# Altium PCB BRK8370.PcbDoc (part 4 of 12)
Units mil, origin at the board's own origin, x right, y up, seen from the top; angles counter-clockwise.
Board outline 8267.72 x 5708.66 mil, 6 copper layers (L1-TOP, L2-GND, L3-PWR, L4-PWR, L5-GND, L6-BOT), stack 68.606 mil thick; 319 components, 516 nets, 2008 pads, 1743 vias.
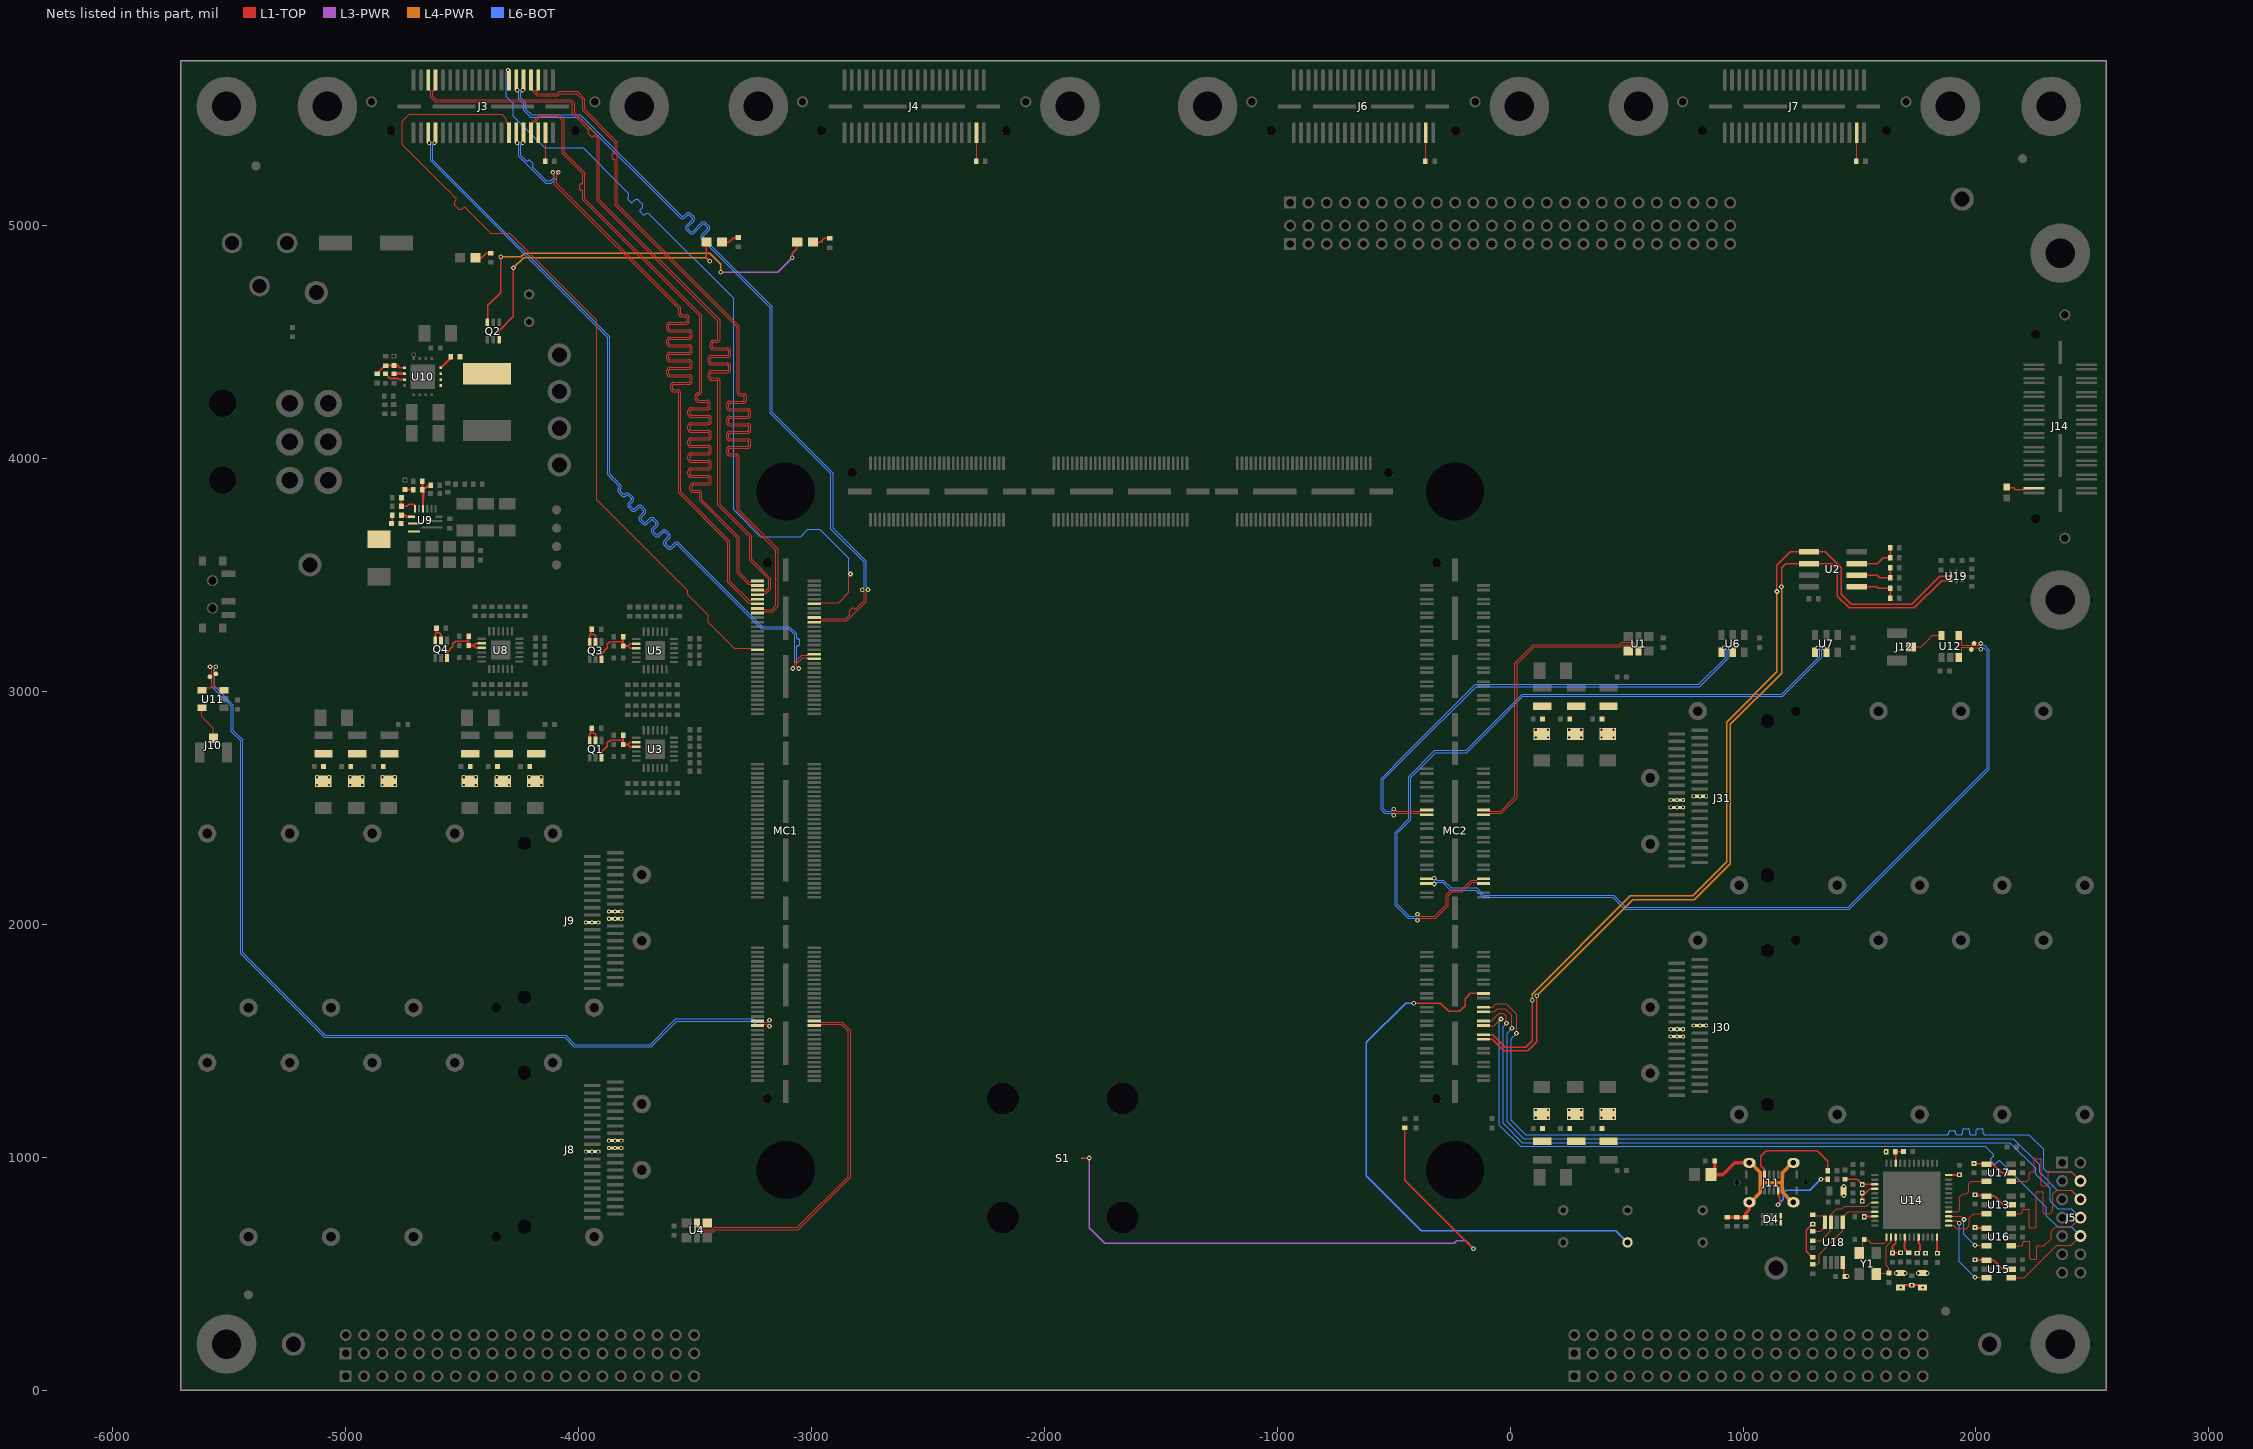
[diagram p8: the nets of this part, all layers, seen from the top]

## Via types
v1: diameter 20, hole 10, L1-TOP to L6-BOT, tented both sides, 957 vias
v2: diameter 18, hole 10, L1-TOP to L6-BOT, tented both sides, 786 vias

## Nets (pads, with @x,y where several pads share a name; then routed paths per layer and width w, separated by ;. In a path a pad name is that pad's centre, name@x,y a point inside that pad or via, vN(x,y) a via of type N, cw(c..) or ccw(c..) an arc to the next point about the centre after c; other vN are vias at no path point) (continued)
EECS: R101.2 U14.45 U18.1 | length 415.2
  L1-TOP w4.96: R101.2@1299.21,539.37 1318.9,539.37 1326.77,547.24 1326.77,582.68 1428.15,684.06 U18.1@1428.15,720.47 1434.53,726.85 1434.53,748.31 1451.97,765.75 U14.45@1565.94,765.75
EEDATA: R102.1 U14.43 U18.3 | length 374.8
  L1-TOP w4.96: R102.1@1299.21,641.73 1334.54,641.73 1376.97,684.17 U18.3@1376.97,720.47 1376.97,753.18 1402.63,778.84 1425.88,778.84 1436.62,789.58 1529.74,789.58 1545.28,805.12 U14.43@1565.94,805.12
EEPROM_A0: R6.1 R9.2 U2.1 | length 189
  L1-TOP w6: U2.1@1488.19,3448.62 1575,3448.62 1579.95,3443.67 R6.1@1631.86,3443.67 R9.2@1631.86,3400.36
EEPROM_A1: R5.1 R8.2 U2.2 | length 191.8
  L1-TOP w6: U2.2@1488.19,3498.62 1576.18,3498.62 1587.83,3486.98 R8.2@1631.86,3486.98 R5.1@1631.86,3530.28
EEPROM_A2: R3.1 R7.2 U2.3 | length 197.3
  L1-TOP w6: U2.3@1488.19,3548.62 1576.18,3548.62 1601.15,3573.59 R7.2@1631.86,3573.59 R3.1@1631.86,3616.9
EEPROM_DO: R102.2 R103.1 U18.4 | length 158.5
  L1-TOP w4.96: R102.2@1299.21,681.1 1334.65,681.1 1345.52,691.98 1345.52,714.61 U18.4@1351.38,720.47 1351.38,740.16 1342.52,749.02 1302.17,749.02 R103.1@1299.21,751.97
FPGA_JTAG_TCK: J5.6 MC2.22 U13.4 | length 3951.4
  L1-TOP w4.96: MC2.22@-114.57,1624.02 -68.47,1624.02 -54.69,1637.8 -21.27,1637.8 7.9,1608.62 v1(7.9,1552.81) ; U13.4@2151.57,757.87 2190.14,757.87 2192.62,757.87 ccw(c2192.62,763.87) 2198.62,763.87 2198.62,771.17 cw(c2204.61,771.17) 2204.61,777.16 2222.59,777.16 cw(c2222.59,771.17) 2228.58,771.17 2228.58,701.84 ccw(c2234.57,701.84) 2234.57,695.85 2252.55,695.85 ccw(c2252.55,701.84) 2258.54,701.84 2258.54,846.15 cw(c2264.53,846.15) 2264.53,852.14 2282.51,852.14 cw(c2282.51,846.15) 2288.5,846.15 2288.5,763.87 ccw(c2294.5,763.87) 2294.5,757.87 2312.43,757.87 2316.81,757.87 2330.4,771.46 2330.4,842.03 2346.64,858.27 2409.45,858.27 J5.6@2448.82,818.9
  L6-BOT w4.96: v1(7.9,1552.81) -13.03,1531.88 -13.03,1151.82 59.02,1079.78 2161,1079.78 2274.08,966.69 2274.08,934.52 2350.33,858.27 2409.45,858.27 J5.6@2448.82,818.9
FPGA_JTAG_TDI: J5.10 MC2.18 U15.4 | length 3673.1
  L1-TOP w4.96: MC2.18@-114.57,1564.96 -67.81,1564.96 v1(-39.44,1593.33) ; U15.4@2151.57,482.28 2207.3,482.28 2347.07,622.05 2409.45,622.05 J5.10@2448.82,661.42
  L6-BOT w4.96: v1(-39.44,1593.33) -39.44,1590.7 -46.95,1583.19 -46.95,1137.77 44.97,1045.85 2040.33,1045.85 2054.56,1031.62 2056.31,1029.87 2074.53,1011.65 cw(c2070.29,1007.41) 2074.53,1003.17 2064.31,992.96 ccw(c2068.55,988.72) 2064.31,984.48 2077.03,971.77 ccw(c2081.26,976.01) 2085.5,971.77 2095.72,981.99 cw(c2099.96,977.75) 2104.19,981.99 2105.95,980.23 2301.93,784.25 2301.93,749.37 2350.52,700.79 2409.45,700.79 J5.10@2448.82,661.42
FPGA_JTAG_TDO: J5.8 MC2.20 U16.4 | length 3781.9
  L1-TOP w4.96: MC2.20@-114.57,1584.65 -79.8,1584.65 -47.27,1617.18 -28.88,1617.18 -15.75,1604.05 v1(-15.75,1574.8) ; U16.4@2151.57,620.08 2193.59,620.08 2196.07,620.08 ccw(c2196.07,626.07) 2202.07,626.07 2202.07,633.38 cw(c2208.06,633.38) 2208.06,639.37 2226.04,639.37 cw(c2226.04,633.38) 2232.03,633.38 2232.03,567 ccw(c2238.02,567) 2238.02,561 2256,561 ccw(c2256,567) 2261.99,567 2261.99,614.09 cw(c2267.99,614.09) 2267.99,620.08 2293.31,620.08 2294.17,620.94 2322.83,649.61 2322.83,681.1 2342.52,700.79 2409.45,700.79 J5.8@2448.82,740.16
  L6-BOT w4.96: v1(-15.75,1574.8) -29.99,1560.56 -29.99,1144.8 51.99,1062.82 2145.85,1062.82 2257.12,951.54 2257.12,927.49 2318.9,865.72 2318.9,811.52 2351.29,779.12 2409.85,779.12 J5.8@2448.82,740.16
FPGA_JTAG_TMS: J5.4 MC2.24 U17.4 | length 3897.9
  L1-TOP w4.96: MC2.24@-114.57,1643.7 -75.32,1643.7 -61.42,1657.6 -16.32,1657.6 27.56,1613.72 v1(27.56,1531.5) ; U17.4@2151.57,895.67 2218.5,895.67 2228.35,905.51 2228.35,929.13 2236.22,937.01 2242.51,937.01 2244.99,937.01 ccw(c2244.99,943) 2250.98,943 2250.98,987.75 cw(c2256.97,987.75) 2256.97,993.75 2274.95,993.75 cw(c2274.95,987.75) 2280.94,987.75 2280.94,882.31 ccw(c2286.94,882.31) 2286.94,876.31 2304.91,876.31 ccw(c2304.91,882.31) 2310.91,882.31 2310.91,931.02 cw(c2316.9,931.02) 2316.9,937.01 2341.6,937.01 2409.45,937.01 J5.4@2448.82,897.64
  L6-BOT w4.96: v1(27.56,1531.5) 3.94,1507.87 3.94,1158.85 66.05,1096.74 1842.52,1096.74 1876.62,1096.74 ccw(c1876.62,1102.73) 1882.61,1102.73 1882.61,1107.25 cw(c1888.61,1107.25) 1888.61,1113.25 1906.58,1113.25 cw(c1906.58,1107.25) 1912.58,1107.25 1912.58,1102.73 ccw(c1918.57,1102.73) 1918.57,1096.74 1936.55,1096.74 ccw(c1936.55,1102.73) 1942.54,1102.73 1942.54,1115.75 cw(c1948.53,1115.75) 1948.53,1121.74 1966.51,1121.74 cw(c1966.51,1115.75) 1972.5,1115.75 1972.5,1102.73 ccw(c1978.5,1102.73) 1978.5,1096.74 1996.47,1096.74 ccw(c1996.47,1102.73) 2002.47,1102.73 2002.47,1115.75 cw(c2008.46,1115.75) 2008.46,1121.74 2026.44,1121.74 cw(c2026.44,1115.75) 2032.43,1115.75 2032.43,1102.73 ccw(c2038.42,1102.73) 2038.42,1096.74 2070.87,1096.74 2227.19,1096.74 2291.05,1032.89 2291.05,950.93 2304.97,937.01 2409.45,937.01 J5.4@2448.82,897.64
FT232_RESET: C76.2 R96.1 U14.34 | length 86.1
  L1-TOP w6: U14.34@1655.51,973.43 1655.51,1021.65 R96.1@1653.54,1023.62 C76.2@1688.58,1023.62
FT232_VCCD: C7.2 C58.2 C62.2 C63.2 C64.2 C68.2 C69.2 C70.2 C74.2 C80.2 C82.2 FB1.1 FB2.1 R96.2 R100.2 R103.2 U13.1 U13.5 U14.12 U14.24 U14.39 U14.46 U15.1 U15.5 U16.1 U17.1 U17.5 U18.8 | length 1226.5
  L1-TOP w6: R100.2@1299.21,570.87 1297.24,570.87 1271.65,596.46 1271.65,687.01 1297.24,712.6 v1(1299.21,712.6)
  L1-TOP w8: U18.8@1428.15,547.24 1432.78,542.62 1432.78,495.02 1434.48,493.31 1442.52,493.31 C82.2@1437.4,488.19 v1(1447.64,488.19) ; C68.2@1437.01,905.12 1489.57,905.12 1512.2,882.48 v1(1512.2,881.89) 1513.82,883.51 1565.59,883.51 U14.39@1565.94,883.86 ; v1(1520.08,744.09) 1521.69,745.71 1565.59,745.71 U14.46@1565.94,746.06 ; U14.12@1832.68,656.5 1832.76,656.42 1832.76,589.29 v1(1834.65,587.4) ; U14.24@1882.87,923.23 1883.23,923.58 1927.91,923.58 v1(1929.13,924.8) ; v1(1992.13,972.83) 1993.31,971.65 2044.09,971.65 U17.1@2045.28,970.47 2072.83,970.47 2110.24,933.07 U17.5@2151.57,933.07 ; v1(1996.06,559.84) 1997.44,558.46 2043.9,558.46 U15.1@2045.28,557.09 2076.77,557.09 2114.17,519.69 U15.5@2151.57,519.69 ; v1(1996.06,697.64) 1997.44,696.26 2043.9,696.26 U16.1@2045.28,694.88 ; v1(1996.06,838.98) 1999.21,835.83 2042.13,835.83 U13.1@2045.28,832.68 2080.71,832.68 2118.11,795.28 U13.5@2151.57,795.28
  L1-TOP w10: v1(1677.17,440.16) 1683.66,440.16 1694.43,450.92 C7.2@1723.88,450.92 ; C7.2@1724.94,450.92 1754.39,450.92 1765.16,440.16 v1(1771.65,440.16)
  other v1: 1724.41,450.39 1614.17,1023.62
FT232_VREGIN: C66.2 C67.2 FB3.1 U14.40 | length 97.1
  L1-TOP w8: v1(1512.2,811.02) v1(1512.2,846.46) ; C67.2@1512.2,847.05 v1(1512.2,846.46) ; U14.40@1565.94,864.17 1545.22,864.17 1527.5,846.46 v1(1512.2,846.46)
  other v1: 1432.28,835.04 1432.28,873.62
FTDI_TCK: U13.3 U14.13 | length 215.8
  L1-TOP w4.96: U14.13@1882.87,706.69 1903.54,706.69 1917.32,692.91 1960.63,692.91 1972.44,704.72 1972.44,740.16 1990.16,757.87 U13.3@2045.28,757.87
FTDI_TDI: U14.14 U15.3 | length 360.4
  L1-TOP w4.96: U14.14@1882.87,726.38 1919.29,726.38 v1(1929.13,716.54) ; v1(1996.06,484.25) 2043.31,484.25 U15.3@2045.28,482.28
  L6-BOT w4.96: v1(1929.13,716.54) 1929.13,551.18 v1(1996.06,484.25)
FTDI_TDO: U14.15 U16.3 | length 251.5
  L1-TOP w4.96: U14.15@1882.87,746.06 1935.04,746.06 v1(1948.82,732.28) ; v1(1996.06,622.05) 2043.31,622.05 U16.3@2045.28,620.08
  L6-BOT w4.96: v1(1948.82,732.28) 1948.82,669.29 v1(1996.06,622.05)
FTDI_TMS: U14.16 U17.3 | length 269.3
  L1-TOP w4.96: U14.16@1882.87,765.75 1923.23,765.75 1931.55,774.07 1931.55,829.19 1944.88,842.52 1960.63,842.52 1968.5,850.39 1968.5,885.83 1978.35,895.67 U17.3@2045.28,895.67
FX3_SCL_1V8: MC2.14 U2.6 U19.3 | length 3818.6
  L1-TOP w6: MC2.14@-114.57,1505.91 -76.77,1505.91 -27.56,1456.69 74.8,1456.69 114.17,1496.06 v1(114.17,1692.91) ; v1(1165.35,3448.82) 1165.35,3530.95 1183.03,3548.62 U2.6@1283.46,3548.62 1380.51,3548.62 1405.51,3523.62 1405.51,3409.45 1456.69,3358.27 1736.22,3358.27 1852.36,3474.41 U19.3@1892.52,3474.41
  L4-PWR w6: v1(114.17,1692.91) 527.56,2106.3 791.34,2106.3 944.88,2259.84 944.88,2858.27 1165.35,3078.74 v1(1165.35,3448.82)
FX3_SDA_1V8: MC2.16 U2.5 U19.2 | length 3856.2
  L1-TOP w6: MC2.16@-114.57,1525.59 -74.67,1525.59 -21.52,1472.44 66.93,1472.44 94.49,1500 v1(94.49,1673.23) ; v1(1145.67,3429.13) 1145.67,3542.22 1202.07,3598.62 U2.5@1283.46,3598.62 1354.13,3598.62 1421.26,3531.5 1421.26,3417.32 1464.57,3374.02 1724.41,3374.02 1844.49,3494.09 U19.2@1892.52,3494.09
  L4-PWR w6: v1(94.49,1673.23) 94.49,1699.78 516.76,2122.05 783.46,2122.05 929.13,2267.72 929.13,2867.69 1145.67,3084.22 v1(1145.67,3429.13)
GNDADC: MC2.28 TP4.1 | length 2450.2
  L1-TOP w6: v1(-413.39,1661.42) -299.21,1661.42 -263.78,1625.98 -216.54,1625.98 -192.91,1649.61 -192.91,1681.1 -171.26,1702.76 MC2.28@-114.57,1702.76
  L6-BOT w6: v1(-413.39,1661.42) -448.82,1661.42 -617.31,1492.93 -617.31,919.89 -381.91,684.49 453.3,684.49 TP4.1@503.94,633.86
MGTREFCLK0_130: J10.1 U11.5 | length 151.4
  L1-TOP w4.96: U11.5@-5617.26,2929.17 -5617.26,2891.76 -5567.91,2842.42 J10.1@-5567.91,2798.23
MGTREFCLK0_227: J12.1 U12.5 | length 151.4
  L1-TOP w4.96: J12.1@1721.43,3190.81 1765.61,3190.81 1814.96,3240.16 U12.5@1852.36,3240.16
MGTREFCLK0N_129: MC1.28 U4.5 | length 1584.8
  L1-TOP w3.3: U4.5@-3492.13,716.54 -3492.13,709.65 -3480.98,698.5 -3478.43,698.5 -3476.5,696.57 -3476.5,687.08 -3469.29,679.88 -3419.74,679.88 -3410.57,689.05 -3056.47,689.05 -2832.39,913.13 -2832.39,1543.56 -2868.13,1579.3 -2935.44,1579.3 -2944.58,1579.3 -2960.6,1579.3 -2965.94,1584.65 MC1.28@-2988.58,1584.65
MGTREFCLK0N_130: MC1.27 TP24.1 U11.3 | length 3959.2
  L1-TOP w3.3: v1(-5557.51,3105.69) -5557.51,3103.41 -5565.51,3095.41 -5565.51,3060.24 -5565.52,3018.03 -5563.58,3016.1 -5534.9,3016.1 U11.3@-5522.77,3003.97 ; MC1.27@-3231.89,1584.65 -3209.25,1584.65 -3203.91,1579.3 -3199.59,1579.3 -3190.6,1579.3 -3182.6,1587.3 v1(-3180.32,1587.3)
  L6-BOT w3.3: v1(-5557.51,3105.69) -5557.51,3103.41 -5565.51,3095.41 -5565.51,3073.68 -5565.52,3024.55 -5482,2941.04 -5482,2830.8 -5442.71,2791.51 -5442.71,1878.13 -5087.41,1522.83 -4055.82,1522.83 -4016.12,1483.13 -3692.61,1483.13 -3582.37,1593.36 -3250.19,1593.36 -3236.13,1579.3 -3190.6,1579.3 -3182.6,1587.3 v1(-3180.32,1587.3)
MGTREFCLK0N_225: MC2.67 U6.5 | length 2097.8
  L1-TOP w3.3: v1(-500,2493.5) -497.72,2493.5 -489.72,2485.5 -471.51,2485.5 -470.82,2484.82 -433.07,2484.82 -385.85,2484.82 -380.51,2490.16 MC2.67@-357.87,2490.16 ; v1(944.59,3187.99) 956.69,3175.89 U6.5@956.69,3167.32
  L6-BOT w3.3: v1(-500,2493.5) -502.28,2493.5 -510.28,2485.5 -534.34,2485.5 -544.99,2496.16 -544.99,2621.79 -433.07,2733.71 -145.97,3020.81 -61.42,3020.81 814.49,3020.81 936.59,3142.9 936.59,3177.71 944.59,3185.71 v1(944.59,3187.99)
MGTREFCLK0N_226: MC2.68 U1.5 | length 1329.9
  L1-TOP w3.3: MC2.68@-114.57,2490.16 -91.93,2490.16 -86.59,2484.82 -70.57,2484.82 -61.42,2484.82 -41.15,2484.82 20.81,2546.78 20.81,3121.74 99.74,3200.67 469.58,3200.67 478.8,3209.89 528.35,3209.89 535.55,3202.68 535.55,3193.2 537.49,3191.26 540.04,3191.26 551.18,3180.12 U1.5@551.18,3173.23
MGTREFCLK0N_227: MC2.47 TP26.1 U12.3 | length 3346
  L1-TOP w3.3: U12.3@1927.17,3145.67 1939.29,3157.8 1939.29,3186.48 1941.23,3188.41 1975.42,3188.41 1975.52,3188.31 2010.36,3188.31 2018.36,3180.31 v1(2020.64,3180.31)
  L6-BOT w3.3: v1(-325.98,2197.54) -323.7,2197.54 -315.7,2189.54 -286.18,2189.54 -252.35,2155.71 -143.93,2155.71 -112.51,2124.3 -61.42,2124.3 445.14,2124.3 496.32,2073.12 1452.66,2073.12 2048.37,2668.83 2048.37,3173.72 2033.78,3188.31 2030.92,3188.31 2022.92,3180.31 v1(2020.64,3180.31)
MGTREFCLK0N_228: MC2.48 U7.5 | length 3108.7
  L1-TOP w3.3: v1(-397.64,2042.31) -395.35,2042.31 -387.35,2034.31 -322.94,2034.31 -274.49,2082.75 -274.49,2127.06 -253.07,2148.48 -208.36,2148.48 -167.3,2189.54 -142.55,2189.54 -137.2,2194.88 MC2.48@-114.57,2194.88 ; v1(1346.16,3187.99) 1358.27,3175.89 U7.5@1358.27,3167.32
  L6-BOT w3.3: v1(-397.64,2042.31) -399.92,2042.31 -407.92,2034.31 -433.07,2034.31 -433.54,2034.31 -485.38,2086.15 -485.38,2390.23 -433.07,2442.54 -426.88,2448.72 -426.88,2629.83 -319.36,2737.35 -185.51,2737.35 -61.42,2861.43 55.21,2978.06 1169.55,2978.06 1338.16,3146.68 1338.16,3177.71 1346.16,3185.71 v1(1346.16,3187.99)
MGTREFCLK0P_129: MC1.26 U4.4 | length 1540.8
  L1-TOP w3.3: U4.4@-3447.83,716.54 -3448.82,716.54 -3466.85,698.5 -3466.85,697.21 -3467.5,696.57 -3467.5,690.81 -3465.57,688.88 -3423.47,688.88 -3414.3,698.05 -3060.2,698.05 -2841.39,916.86 -2841.39,1539.84 -2871.86,1570.3 -2935.44,1570.3 -2940.86,1570.3 -2960.6,1570.3 -2965.94,1564.96 MC1.26@-2988.58,1564.96
MGTREFCLK0P_130: MC1.25 TP23.1 U11.4 | length 3974.1
  L1-TOP w3.3: U11.4@-5617.26,3003.97 -5605.13,3016.1 -5576.45,3016.1 -5574.52,3018.03 -5574.52,3059.06 -5574.52,3064.73 -5574.51,3095.41 -5582.51,3103.41 v1(-5582.51,3105.69) ; MC1.25@-3231.89,1564.96 -3209.25,1564.96 -3203.91,1570.3 -3195.86,1570.3 -3190.6,1570.3 -3182.6,1562.3 v1(-3180.32,1562.3)
  L6-BOT w3.3: v1(-5582.51,3105.69) -5582.51,3103.41 -5574.51,3095.41 -5574.51,3078.18 -5574.52,3020.83 -5491,2937.31 -5491,2827.08 -5451.71,2787.79 -5451.71,1874.4 -5091.14,1513.83 -4059.55,1513.83 -4019.85,1474.13 -3688.88,1474.13 -3578.65,1584.36 -3253.92,1584.36 -3239.86,1570.3 -3190.6,1570.3 -3182.6,1562.3 v1(-3180.32,1562.3)
MGTREFCLK0P_225: MC2.65 U6.4 | length 2112.7
  L1-TOP w3.3: v1(-500,2468.5) -497.72,2468.5 -489.72,2476.5 -475.23,2476.5 -474.54,2475.82 -433.07,2475.82 -385.85,2475.82 -380.51,2470.47 MC2.65@-357.87,2470.47 ; U6.4@907.48,3167.32 919.59,3179.43 v1(919.59,3187.99)
  L6-BOT w3.3: v1(-500,2468.5) -502.28,2468.5 -510.28,2476.5 -538.07,2476.5 -553.99,2492.43 -553.99,2625.52 -433.07,2746.44 -149.7,3029.81 -61.42,3029.81 810.77,3029.81 927.59,3146.63 927.59,3177.71 919.59,3185.71 v1(919.59,3187.99)
MGTREFCLK0P_226: MC2.66 U1.4 | length 1315.7
  L1-TOP w3.3: MC2.66@-114.57,2470.47 -91.93,2470.47 -86.59,2475.82 -66.84,2475.82 -61.42,2475.82 -37.42,2475.82 29.81,2543.05 29.81,3118.02 103.47,3191.67 473.31,3191.67 482.53,3200.89 524.62,3200.89 526.55,3198.95 526.55,3193.2 525.91,3192.55 525.91,3191.26 507.87,3173.23 U1.4@506.89,3173.23
MGTREFCLK0P_227: MC2.45 TP25.1 U12.4 | length 3375.8
  L1-TOP w3.3: U12.4@1927.17,3240.16 1939.29,3228.03 1939.29,3199.35 1941.23,3197.41 1979.14,3197.41 1979.25,3197.31 2010.36,3197.31 2018.36,3205.31 v1(2020.64,3205.31)
  L6-BOT w3.3: v1(-325.98,2172.54) -323.7,2172.54 -315.7,2180.54 -289.91,2180.54 -256.08,2146.71 -147.65,2146.71 -116.24,2115.3 -61.42,2115.3 441.41,2115.3 492.59,2064.12 1456.39,2064.12 2057.37,2665.1 2057.37,3177.45 2037.51,3197.31 2030.92,3197.31 2022.92,3205.31 v1(2020.64,3205.31)
MGTREFCLK0P_228: MC2.46 U7.4 | length 3123.6
  L1-TOP w3.3: v1(-397.64,2017.31) -395.35,2017.31 -387.35,2025.31 -319.21,2025.31 -265.49,2079.03 -265.49,2123.33 -249.34,2139.48 -204.63,2139.48 -163.57,2180.54 -142.55,2180.54 -137.2,2175.2 MC2.46@-114.57,2175.2 ; U7.4@1309.06,3167.32 1321.16,3179.43 v1(1321.16,3187.99)
  L6-BOT w3.3: v1(-397.64,2017.31) -399.92,2017.31 -407.92,2025.31 -433.07,2025.31 -437.26,2025.31 -494.38,2082.42 -494.38,2393.96 -435.88,2452.45 -435.88,2633.55 -433.07,2636.37 -323.09,2746.35 -189.23,2746.35 -61.42,2874.15 51.49,2987.06 1165.82,2987.06 1329.16,3150.41 1329.16,3177.71 1321.16,3185.71 v1(1321.16,3187.99)
NetC9_2: C9.2 C57.2 FB1.2 U14.8 | length 76.8
  L1-TOP w8: v1(1748.03,587.4) 1748.62,587.4 1754.86,593.64 1754.86,594.23 1759.84,599.21 1759.84,625.98 1753.94,631.89 U14.8@1753.94,656.5
  other v1: 1752.36,501.57 1790.94,501.57 1783.46,587.4
NetC10_2: C10.2 Q1.6 R2.1 U3.20 U3.21 | length 288
  L1-TOP w6: Q1.6@-3901.57,2714.57 -3901.57,2739.69 -3875.98,2765.28 -3875.98,2779.53 -3865.03,2790.48 -3835.27,2790.48 -3835.19,2790.4 -3808.86,2790.4
  L1-TOP w8: R2.1@-3809.06,2811.02 -3808.86,2810.83 -3808.86,2790.4 -3808.86,2771.85 C10.2@-3808.66,2771.65 -3788.33,2771.65 ; U3.21@-3751.97,2761.81 -3778.49,2761.81 -3788.33,2771.65 ; U3.20@-3751.97,2781.5 -3778.49,2781.5 -3788.33,2771.65
NetC13_2: C13.2 C14.2 J8.30 L1.2
  other v2: -3869.77,1070.87 -3843.31,1070.87 -3816.84,1070.87 -4841.95,2598.09 -4789.95,2598.09 -4841.95,2631.01 -4789.95,2631.01
NetC15_2: C15.2 C16.2 J8.29 L2.2
  other v2: -3869.77,1039.37 -3843.31,1039.37 -3816.84,1039.37 -5123.44,2598.09 -5071.44,2598.09 -5123.44,2631.01 -5071.44,2631.01
NetC17_2: C17.2 C18.2 J8.10 L3.2
  other v2: -3968.59,1023.62 -3942.13,1023.62 -3915.66,1023.62 -4980.72,2598.09 -4928.72,2598.09 -4980.72,2631.01 -4928.72,2631.01
NetC21_2: C21.2 C22.2 J9.30 L4.2
  other v2: -3869.77,2055.12 -3843.31,2055.12 -3816.84,2055.12 -4212.02,2598.09 -4160.02,2598.09 -4212.02,2631.01 -4160.02,2631.01
NetC23_2: C23.2 C24.2 J9.29 L11.2
  other v2: -3869.77,2023.62 -3843.31,2023.62 -3816.84,2023.62 -4493.52,2598.09 -4441.52,2598.09 -4493.52,2631.01 -4441.52,2631.01
NetC25_2: C25.2 C26.2 J9.10 L12.2
  other v2: -3968.59,2007.87 -3942.13,2007.87 -3915.66,2007.87 -4350.8,2598.09 -4298.8,2598.09 -4350.8,2631.01 -4298.8,2631.01
NetC31_2: C31.2 Q3.6 R35.1 U5.20 U5.21 | length 288
  L1-TOP w6: Q3.6@-3901.57,3137.8 -3901.57,3161.12 -3875.98,3186.71 -3875.98,3202.76 -3865.03,3213.71 -3835.27,3213.71 -3835.19,3213.63 -3808.86,3213.63
  L1-TOP w8: R35.1@-3809.06,3234.25 -3808.86,3234.06 -3808.86,3213.63 -3808.86,3195.08 C31.2@-3808.66,3194.88 -3788.33,3194.88 ; U5.21@-3751.97,3185.04 -3778.49,3185.04 -3788.33,3194.88 ; U5.20@-3751.97,3204.72 -3778.49,3204.72 -3788.33,3194.88
NetC33_2: C33.2 Q4.6 R55.1 U8.20 U8.21 | length 284.1
  L1-TOP w6: Q4.6@-4564.96,3143.7 -4564.96,3167.32 -4539.37,3192.91 -4539.37,3204.72 -4528.42,3215.68 -4498.65,3215.68 -4498.58,3215.6 -4472.24,3215.6
  L1-TOP w8: R55.1@-4472.44,3236.22 -4472.24,3236.02 -4472.24,3215.6 -4472.24,3197.05 C33.2@-4472.05,3196.85 -4451.72,3196.85 ; U8.21@-4415.35,3187.01 -4441.88,3187.01 -4451.72,3196.85 ; U8.20@-4415.35,3206.69 -4441.88,3206.69 -4451.72,3196.85
NetC39_1: C39.1 R64.2 | length 37.8
  L1-TOP w6: C39.1@-4803.11,3720.59 -4799.92,3723.78 R64.2@-4799.92,3757.1
NetC39_2: C39.2 L13.1 U9.2 U9.3
NetC40_1: C40.1 R68.2 | length 34.7
  L1-TOP w9: C40.1@-4744.76,3867.03 -4711.36,3867.03 R68.2@-4710.44,3866.11
NetC53_1: C53.1 U10.12 | length 67.2
  L1-TOP w10: U10.12@-4593.71,4390.37 -4589.73,4390.37 -4549.41,4430.69 C53.1@-4549.41,4436.87
NetC53_2: C53.2 L14.1 U10.9 U10.10 U10.11
NetC54_1: C54.1 R77.1 R78.2 U10.1 | length 138.8
  L1-TOP w8: R78.2@-4865.25,4363.55 -4865.25,4366.87 -4832.94,4399.18 -4829.25,4399.18 R77.1@-4828.86,4398.79 -4793.25,4398.79 -4776.17,4398.79 -4767.15,4389.76 U10.1@-4747.05,4389.76
NetC55_2: C55.2 U10.3 | length 92.7
  L1-TOP w8: C55.2@-4829.25,4363.94 -4808.11,4342.81 -4774.19,4342.81 -4769.97,4338.58 U10.3@-4747.05,4338.58
NetC56_2: C56.2 U10.2 | length 46.3
  L1-TOP w13: C56.2@-4793.25,4363.94 -4793.02,4364.17 U10.2@-4747.05,4364.17
NetC60_2: C60.2 C61.2 FB2.2 U14.3 | length 108.8
  L1-TOP w7: v1(1641.73,588.98) 1641.93,589.17 v1(1676.97,589.17) C61.2@1677.17,589.37
  L1-TOP w8: v1(1641.73,588.98) 1641.73,617.28 1655.51,631.06 U14.3@1655.51,656.5
  other v1: 1657.87,501.57 1696.46,501.57
NetC77_2: C77.2 FB4.1 J11.M1 J11.M2 J11.M3 J11.M4 R97.1 R98.1 R99.1 | length 924.3
  L1-TOP w15: C77.2@878.35,984.25 878.35,965.93 878.33,941.32 FB4.1@862.2,925.2 913.39,925.2 963.78,975.59 J11.M3@1027.56,975.59 ; R97.1@933.07,742.13 R98.1@972.44,742.13 R99.1@1011.81,742.13 1011.81,759.84 1027.56,775.59 J11.M2@1027.56,806.3
  L4-PWR w15: J11.M2@1027.56,806.3 1032.48,806.3 1074.8,848.62 1074.8,890.94 ; J11.M3@1027.56,975.59 1032.48,975.59 1074.8,933.27 1074.8,890.94 ; J11.M1@1216.54,806.3 1211.61,806.3 1169.29,848.62 1169.29,890.94 ; J11.M4@1216.54,975.59 1211.61,975.59 1169.29,933.27 1169.29,890.94 ; 1074.8,890.94 1169.29,890.94
NetC78_2: C78.2 U14.1 Y1.1 | length 189.8
  L1-TOP w4.96: Y1.1@1499.02,588.58 1514.75,604.32 1514.75,640.34 C78.2@1520.08,645.67 1535.43,645.67 1551.18,629.92 1607.39,629.92 1616.14,638.68 U14.1@1616.14,656.5
NetC79_2: C79.2 U14.2 Y1.3 | length 223.9
  L1-TOP w4.96: Y1.3@1571.85,498.03 1576.18,502.36 C79.2@1625.98,502.36 1625.98,523.62 1614.17,535.43 1614.17,618.11 1635.83,639.76 U14.2@1635.83,656.5
NetC90_2: C90.2 C91.2 J30.29 L6.2
  other v2: 253.31,1169.29 305.31,1169.29 253.31,1202.21 305.31,1202.21 689.68,1549.21 716.14,1549.21 742.61,1549.21
NetC92_2: C92.2 C93.2 J30.10 L7.2
  other v2: 110.6,1169.29 162.6,1169.29 110.6,1202.21 162.6,1202.21 788.5,1564.96 814.96,1564.96 841.43,1564.96
NetC94_2: C94.2 C95.2 J30.30 L5.2
  other v2: 392.09,1169.29 444.09,1169.29 392.09,1202.21 444.09,1202.21 689.68,1517.72 716.14,1517.72 742.61,1517.72
NetC102_2: C102.2 C103.2 J31.29 L9.2
  other v2: 689.68,2533.46 716.14,2533.46 742.61,2533.46 392.09,2801.72 444.09,2801.72 392.09,2834.65 444.09,2834.65
NetC104_2: C104.2 C105.2 J31.10 L10.2
  other v2: 788.5,2549.21 814.96,2549.21 841.43,2549.21 110.6,2801.72 162.6,2801.72 110.6,2834.65 162.6,2834.65
NetC106_2: C106.2 C107.2 J31.30 L8.2
  other v2: 689.68,2501.97 716.14,2501.97 742.61,2501.97 253.31,2801.72 305.31,2801.72 253.31,2834.65 305.31,2834.65
NetD1_2: D1.2 R4.1 | length 73.1
  L1-TOP w6: D1.2@-4442.91,4862.2 -4415.63,4862.2 -4395.95,4881.89 R4.1@-4377.95,4881.89
NetD2_1: D2.1 Q2.6 | length 1289.8
  L1-TOP w6: Q2.6@-4340.55,4509.84 -4340.55,4548.73 -4279.53,4609.75 v1(-4279.53,4818.9) ; D2.1@-3450.79,4929.13 -3450.79,4860.24 v1(-3437.01,4846.46)
  L4-PWR w6: v1(-4279.53,4818.9) -4236.15,4862.27 -3452.82,4862.27 v1(-3437.01,4846.46)
NetD2_2: D2.2 R12.1 | length 77.1
  L1-TOP w6: D2.2@-3383.86,4929.13 -3354.33,4929.13 -3334.65,4948.82 R12.1@-3314.96,4948.82
NetD3_1: D3.1 Q2.3 | length 1720.6
  L1-TOP w6: Q2.3@-4391.73,4584.65 -4389.76,4586.61 -4389.76,4657.48 -4334.65,4712.6 v1(-4334.65,4866.14) ; v1(-3082.68,4862.2) -3082.68,4881.89 -3062.99,4901.57 -3062.99,4927.17 D3.1@-3061.02,4929.13
  L3-PWR w6: v1(-3389.76,4799.21) -3145.67,4799.21 v1(-3082.68,4862.2)
  L4-PWR w6: v1(-4334.65,4866.14) -4247.84,4866.14 -4232.09,4881.89 -3437.01,4881.89 -3389.76,4834.65 v1(-3389.76,4799.21)
NetD3_2: D3.2 R92.1 | length 79.4
  L1-TOP w6: D3.2@-2994.09,4929.13 -2960.63,4929.13 -2944.88,4944.88 R92.1@-2921.26,4944.88
NetD4_1,10: D4.1 D4.10 | length 30.5
  L1-TOP w5: D4.10@1161.42,718.21 D4.1@1161.42,748.72
NetJ3_4: J3.4 R66.2 | length 122
  L1-TOP w5: J3.4@-4141.65,5399.01 -4141.6,5277.41 R66.2@-4141.34,5277.15
NetJ4_4: J4.4 R67.2 | length 122
  L1-TOP w5: J4.4@-2291.26,5399.01 -2291.21,5277.41 R67.2@-2290.94,5277.15
NetJ6_4: J6.4 R10.2 | length 122
  L1-TOP w5: J6.4@-362.07,5399.01 -362.07,5277.41 R10.2@-361.81,5277.15
NetJ7_4: J7.4 R11.2 | length 122
  L1-TOP w5: J7.4@1488.27,5399.01 1488.32,5277.41 R11.2@1488.58,5277.15
NetJ11_A5: J11.A5 R93.2 | length 342
  L1-TOP w6: v1(1150.25,795.84) 1150.25,799.17 1157.44,806.35 1157.44,828.18 1151.57,834.05 J11.A5@1151.57,856.89 ; v1(1334.65,905.51) R93.2@1364.17,905.51
  L6-BOT w6: v1(1150.25,795.84) 1173.23,818.82 1173.23,846.46 1185.04,858.27 1287.4,858.27 v1(1334.65,905.51)
NetJ11_B5: J11.B5 R94.1 | length 442.7
  L1-TOP w6: J11.B5@1092.52,925 1092.52,946.85 1076.53,962.84 1076.53,1003.32 1100.77,1027.56 1318.9,1027.56 1364.17,982.28 R94.1@1364.17,940.94
NetJ14_4: J14.4 R27.2 | length 122.7
  L1-TOP w6: R27.2@2132.05,3873.97 2161.46,3873.97 2169.29,3866.14 2202.62,3866.14 2205.57,3869.09 2246.7,3869.09 J14.4@2249.21,3871.6
NetQ1_2: Q1.2 Q1.3 R1.1 | length 104.1
  L1-TOP w6: Q1.3@-3952.76,2789.37 -3952.76,2816.93 -3946.85,2822.83 ; R1.1@-3946.85,2842.52 -3946.85,2822.83 ; Q1.2@-3927.17,2789.37 -3927.17,2814.96 -3935.04,2822.83 -3946.85,2822.83
NetQ3_2: Q3.2 Q3.3 R34.1 | length 104.1
  L1-TOP w6: Q3.3@-3952.76,3212.6 -3952.76,3240.16 -3946.85,3246.06 ; R34.1@-3946.85,3265.75 -3946.85,3246.06 ; Q3.2@-3927.17,3212.6 -3927.17,3238.19 -3935.04,3246.06 -3946.85,3246.06
NetQ4_2: Q4.2 Q4.3 R54.1 | length 104.1
  L1-TOP w6: Q4.3@-4616.14,3218.5 -4616.14,3246.06 -4610.24,3251.97 ; R54.1@-4610.24,3271.65 -4610.24,3251.97 ; Q4.2@-4590.55,3218.5 -4590.55,3244.09 -4598.43,3251.97 -4610.24,3251.97
NetR64_1: R64.1 U9.1 | length 45.8
  L1-TOP w9: R64.1@-4760.55,3757.1 -4745.86,3757.1 -4738.73,3749.98 U9.1@-4717.67,3749.98
NetR65_1: R65.1 R68.1 R70.2 U9.10 | length 161.8
  L1-TOP w9: R68.1@-4671.15,3866.19 -4671.15,3882.42 -4671.07,3882.5 R65.1@-4671.07,3902.11 ; U9.10@-4667.47,3784.66 -4667.14,3866.09 -4667.14,3872.01 -4665.73,3873.42 -4657.59,3873.42 -4652.53,3878.48 -4640.85,3878.48 -4635.51,3883.83 R70.2@-4635.51,3885.8
NetR71_1: R71.1 R73.2 U9.12 | length 114.2
  L1-TOP w6: R71.1@-4760.51,3830.94 R73.2@-4760.51,3793.94 -4738.2,3793.94 -4727.99,3804.15 -4709.99,3804.15 -4702.91,3797.06 U9.12@-4702.91,3784.66
NetR95_2: R95.2 U14.5 | length 77.7
  L1-TOP w8: U14.5@1694.88,656.5 1694.88,631.8 1692.82,629.74 1692.82,607.51 1696.99,603.33 1696.99,602.61 1710.63,588.98 R95.2@1712.6,588.98
NetR104_1: R104.1 S1.2 | length 2668.2
  L1-TOP w6: S1.2@-1838.56,996.06 v1(-1807.09,996.06) ; R104.1@-452.76,1125.98 -452.76,901.57 v1(-157.48,606.3)
  L3-PWR w6: v1(-1807.09,996.06) -1807.09,696.85 -1740.16,629.92 -240.29,629.92 -230.18,640.03 -191.21,640.03 v1(-157.48,606.3)
PORTA_C2P_CLK_N: J3.36 MC1.148 | length 3383
  L1-TOP w3.3: v1(-3080.12,3098.43) -3080.12,3100.71 -3072.12,3108.71 -3072.12,3123.3 -3041.32,3154.11 -3016.56,3154.11 -3011.22,3159.45 MC1.148@-2988.58,3159.45
  L6-BOT w3.3: v2(-4641.53,5355.65) -4641.53,5353.41 -4634.5,5346.37 -4634.5,5277.66 -3875.55,4518.71 -3875.55,3929.75 -3854.79,3908.99 -3851.76,3905.96 -3827.42,3881.62 cw(c-3831.42,3877.62) -3827.42,3873.61 ccw(c-3817.05,3863.25) -3827.39,3852.86 -3815.44,3840.9 ccw(c-3805.04,3851.24) -3794.68,3840.87 -3794.44,3841.11 cw(c-3790.42,3837.13) -3786.42,3841.13 -3774.41,3829.12 cw(c-3778.41,3825.12) -3774.41,3821.12 -3785.01,3810.52 ccw(c-3774.65,3800.15) -3784.99,3789.76 -3773.04,3777.81 ccw(c-3762.64,3788.14) -3752.28,3777.78 -3741.69,3788.36 cw(c-3737.67,3784.38) -3733.67,3788.38 -3721.66,3776.37 cw(c-3725.66,3772.37) -3721.66,3768.37 -3738.44,3751.59 -3738.44,3751.39 ccw(c-3726.76,3742.54) -3737.1,3732.15 ; -3737.1,3732.14 -3725.15,3720.19 ; -3725.14,3720.19 ccw(c-3714.75,3730.53) -3704.39,3720.17 -3688.94,3735.61 cw(c-3684.92,3731.63) -3680.92,3735.63 -3668.91,3723.62 cw(c-3672.91,3719.62) -3668.91,3715.62 -3685.69,3698.84 -3685.69,3698.64 ccw(c-3674.01,3689.79) -3684.35,3679.4 ; -3684.35,3679.39 -3672.4,3667.44 ; -3672.39,3667.44 ccw(c-3662,3677.78) -3651.64,3667.42 -3636.19,3682.86 cw(c-3632.17,3678.88) -3628.17,3682.88 -3616.16,3670.87 cw(c-3620.16,3666.87) -3616.16,3662.87 -3632.94,3646.09 -3632.94,3645.89 ccw(c-3621.26,3637.04) -3631.6,3626.65 ; -3631.6,3626.64 -3619.65,3614.69 ; -3619.64,3614.69 ccw(c-3609.25,3625.03) -3598.89,3614.67 -3583.68,3629.87 cw(c-3579.68,3625.87) -3575.66,3629.86 ; -3575.64,3629.85 -3574.36,3628.56 -3571.32,3625.53 -3215.2,3269.4 -3098.52,3269.4 -3072.12,3243 -3072.12,3108.71 -3080.12,3100.71 v1(-3080.12,3098.43)
PORTA_C2P_CLK_P: J3.34 MC1.146 | length 3383.1
  L1-TOP w3.3: v1(-3055.12,3098.43) -3055.12,3100.71 -3063.12,3108.71 -3063.12,3119.58 -3037.59,3145.11 -3016.56,3145.11 -3011.22,3139.76 MC1.146@-2988.58,3139.76
  L6-BOT w3.3: v2(-4618.46,5355.65) -4618.46,5353.41 -4625.5,5346.37 -4625.5,5281.39 -3866.55,4522.44 -3866.55,3933.48 -3848.43,3915.35 -3845.39,3912.32 -3821.05,3887.98 cw(c-3831.42,3877.62) -3821.05,3867.25 ccw(c-3817.05,3863.25) -3821.06,3859.25 -3809.04,3847.23 ccw(c-3805.04,3851.24) -3801.04,3847.24 -3799.47,3848.81 -3799.27,3848.81 cw(c-3790.42,3837.13) -3780.05,3847.5 -3768.05,3835.49 cw(c-3778.41,3825.12) -3768.02,3814.78 -3778.65,3804.15 ccw(c-3774.65,3800.15) -3778.66,3796.15 -3766.64,3784.14 ccw(c-3762.64,3788.14) -3758.64,3784.14 -3746.72,3796.06 -3746.52,3796.06 cw(c-3737.67,3784.38) -3727.3,3794.75 -3715.3,3782.74 cw(c-3725.66,3772.37) -3715.26,3762.04 -3730.74,3746.56 ; -3730.76,3746.54 ccw(c-3726.76,3742.54) -3730.77,3738.54 -3718.75,3726.52 ccw(c-3714.75,3730.53) -3710.75,3726.53 -3693.97,3743.31 -3693.77,3743.31 cw(c-3684.92,3731.63) -3674.55,3742 -3662.55,3729.99 cw(c-3672.91,3719.62) -3662.51,3709.29 -3677.99,3693.81 ; -3678.01,3693.79 ccw(c-3674.01,3689.79) -3678.02,3685.79 -3666,3673.77 ccw(c-3662,3677.78) -3658,3673.78 -3641.22,3690.56 -3641.02,3690.56 cw(c-3632.17,3678.88) -3621.8,3689.25 -3609.8,3677.24 cw(c-3620.16,3666.87) -3609.76,3656.54 -3625.24,3641.06 ; -3625.26,3641.04 ccw(c-3621.26,3637.04) -3625.27,3633.04 -3613.25,3621.02 ccw(c-3609.25,3625.03) -3605.25,3621.03 -3590.04,3636.24 cw(c-3579.68,3625.87) -3570.82,3637.56 -3570.63,3637.56 -3569.33,3636.26 ; -3569.31,3636.24 -3567.99,3634.92 -3564.96,3631.89 -3211.47,3278.4 -3094.79,3278.4 -3063.12,3246.73 -3063.12,3232.28 -3063.12,3230.63 ccw(c-3057.46,3230.63) -3057.46,3224.97 -3056.47,3224.97 cw(c-3056.47,3219.31) -3050.81,3219.31 -3050.81,3202.33 cw(c-3056.47,3202.33) -3056.47,3196.67 -3057.46,3196.67 ccw(c-3057.46,3191.01) -3063.12,3191.01 -3063.12,3173.23 -3063.12,3108.71 -3055.12,3100.71 v1(-3055.12,3098.43)
PORTA_P2C_CLK_N: J3.35 MC1.175 | length 3563.5
  L1-TOP w3.3: J3.35@-4645.65,5624.61 -4645.65,5587.86 -4639.3,5581.51 -4636.33,5581.51 -4634.4,5579.58 -4634.4,5550.92 -4614.66,5531.19 -4038.29,5531.19 -4026.23,5519.13 -4026.23,5480.42 -4012.8,5466.98 -3966.47,5420.65 -3957.69,5411.88 cw(c-3961.69,5407.87) -3957.69,5403.87 -3958.4,5403.17 ccw(c-3954.39,5399.17) -3958.4,5395.17 -3946.39,5383.16 ccw(c-3942.39,5387.16) -3938.38,5383.16 -3937.68,5383.86 cw(c-3933.68,5379.86) -3929.68,5383.86 -3928.51,5382.69 -3920.13,5374.32 -3920.13,5107.57 -3401.57,4589.01 -3401.57,4578.74 -3401.57,4512 cw(c-3406.23,4512) -3406.23,4507.34 -3421.42,4507.34 ccw(c-3421.42,4493.68) -3435.08,4493.68 -3435.08,4479.7 ccw(c-3421.42,4479.7) -3421.42,4466.04 -3360.86,4466.04 cw(c-3360.86,4461.38) -3356.2,4461.38 -3356.2,4447.4 cw(c-3360.86,4447.4) -3360.86,4442.74 -3429.35,4442.74 ccw(c-3429.35,4429.08) -3443.01,4429.08 -3443.01,4415.1 ccw(c-3429.35,4415.1) -3429.35,4401.44 -3360.86,4401.44 cw(c-3360.86,4396.78) -3356.2,4396.78 -3356.2,4382.8 cw(c-3360.86,4382.8) -3360.86,4378.14 -3429.35,4378.14 ccw(c-3429.35,4364.48) -3443.01,4364.48 -3443.01,4350.5 ccw(c-3429.35,4350.5) -3429.35,4336.84 -3406.23,4336.84 cw(c-3406.23,4332.18) -3401.57,4332.18 -3401.57,4326.03 -3401.57,3798.43 -3265.95,3662.81 -3265.95,3571.46 -3265.95,3562.82 -3183.91,3480.78 -3183.91,3444.18 -3198.4,3429.7 -3203.91,3429.7 -3209.25,3435.04 MC1.175@-3231.89,3435.04
PORTA_P2C_CLK_P: J3.33 MC1.173 | length 3563.5
  L1-TOP w3.3: J3.33@-4614.15,5624.61 -4614.15,5587.86 -4620.5,5581.51 -4623.47,5581.51 -4625.4,5579.58 -4625.4,5554.65 -4610.94,5540.19 -4034.56,5540.19 -4017.23,5522.86 -4017.23,5484.14 -4012.8,5479.71 -3911.13,5378.05 -3911.13,5111.3 -3392.57,4592.74 -3392.57,4578.74 -3392.57,4512 cw(c-3406.23,4512) -3406.23,4498.34 -3421.42,4498.34 ccw(c-3421.42,4493.68) -3426.08,4493.68 -3426.08,4479.7 ccw(c-3421.42,4479.7) -3421.42,4475.04 -3360.86,4475.04 cw(c-3360.86,4461.38) -3347.2,4461.38 -3347.2,4447.4 cw(c-3360.86,4447.4) -3360.86,4433.74 -3429.35,4433.74 ccw(c-3429.35,4429.08) -3434.01,4429.08 -3434.01,4415.1 ccw(c-3429.35,4415.1) -3429.35,4410.44 -3360.86,4410.44 cw(c-3360.86,4396.78) -3347.2,4396.78 -3347.2,4382.8 cw(c-3360.86,4382.8) -3360.86,4369.14 -3429.35,4369.14 ccw(c-3429.35,4364.48) -3434.01,4364.48 -3434.01,4350.5 ccw(c-3429.35,4350.5) -3429.35,4345.84 -3406.23,4345.84 cw(c-3406.23,4332.18) -3392.57,4332.18 -3392.57,4326.03 -3392.57,3802.16 -3256.95,3666.54 -3256.95,3571.46 -3256.95,3566.54 -3174.91,3484.51 -3174.91,3440.45 -3194.67,3420.7 -3203.91,3420.7 -3209.25,3415.35 MC1.173@-3231.89,3415.35
PORTA_S0_D0_P: J3.5 MC1.165 | length 3563.5
  L1-TOP w3.3: J3.5@-4173.15,5624.61 -4173.15,5587.86 -4179.5,5581.51 -4182.47,5581.51 -4184.4,5579.58 -4184.4,5576.11 -4174.78,5566.49 -4092.68,5566.49 -4083.19,5575.98 -4012.8,5575.98 -4006.54,5575.98 -3974.13,5543.56 -3974.13,5498.53 -3833.52,5357.92 -3833.52,5091.17 -3309.9,4567.55 -3309.9,4346.46 -3309.9,4283.55 ccw(c-3305.24,4283.55) -3305.24,4278.89 -3292.39,4278.89 cw(c-3292.39,4265.23) -3278.73,4265.23 -3278.73,4251.25 cw(c-3292.39,4251.25) -3292.39,4237.59 -3350.61,4237.59 ccw(c-3350.61,4232.93) -3355.27,4232.93 -3355.27,4218.95 ccw(c-3350.61,4218.95) -3350.61,4214.29 -3273.56,4214.29 cw(c-3273.56,4200.63) -3259.9,4200.63 -3259.9,4186.65 cw(c-3273.56,4186.65) -3273.56,4172.99 -3350.61,4172.99 ccw(c-3350.61,4168.33) -3355.27,4168.33 -3355.27,4154.35 ccw(c-3350.61,4154.35) -3350.61,4149.69 -3273.56,4149.69 cw(c-3273.56,4136.03) -3259.9,4136.03 -3259.9,4122.05 cw(c-3273.56,4122.05) -3273.56,4108.39 -3350.61,4108.39 ccw(c-3350.61,4103.73) -3355.27,4103.73 -3355.27,4089.75 ccw(c-3350.61,4089.75) -3350.61,4085.09 -3273.56,4085.09 cw(c-3273.56,4071.43) -3259.9,4071.43 -3259.9,4057.45 cw(c-3273.56,4057.45) -3273.56,4043.79 -3350.61,4043.79 ccw(c-3350.61,4039.13) -3355.27,4039.13 -3355.27,4025.15 ccw(c-3350.61,4025.15) -3350.61,4020.49 -3323.56,4020.49 cw(c-3323.56,4006.83) -3309.9,4006.83 -3309.9,4000.68 -3309.9,3776.97 -3143.42,3610.49 -3143.42,3571.46 -3143.42,3365.88 -3167.35,3341.96 -3203.91,3341.96 -3209.25,3336.61 MC1.165@-3231.89,3336.61
PORTA_S1_D1_P: J3.6 MC1.177 | length 3564.4
  L1-TOP w3.3: J3.6@-4173.15,5399.01 -4173.15,5435.76 -4179.5,5442.11 -4182.47,5442.11 -4184.4,5444.04 -4184.4,5447.51 -4161.74,5470.17 -4089.56,5470.17 -4069.79,5450.4 -4069.79,5311.37 -3981.73,5223.31 -3981.73,5215.05 -3981.73,5185.1 cw(c-3987.39,5185.1) -3987.39,5179.44 -3988.38,5179.44 ccw(c-3988.38,5173.78) -3994.04,5173.78 -3994.04,5156.8 ccw(c-3988.38,5156.8) -3988.38,5151.14 -3987.39,5151.14 cw(c-3987.39,5145.48) -3981.73,5145.48 -3981.73,5124.73 -3981.73,5111.67 -3480.32,4610.26 -3480.32,4322.83 -3480.32,4287.57 cw(c-3484.98,4287.57) -3484.98,4282.91 ccw(c-3484.98,4269.25) -3498.64,4269.25 -3498.64,4255.27 ccw(c-3484.98,4255.27) -3484.98,4241.61 -3447.28,4241.61 cw(c-3447.28,4236.95) -3442.62,4236.95 -3442.62,4222.97 cw(c-3447.28,4222.97) -3447.28,4218.31 -3516.66,4218.31 ccw(c-3516.66,4204.65) -3530.32,4204.65 -3530.32,4190.67 ccw(c-3516.66,4190.67) -3516.66,4177.01 -3443.53,4177.01 cw(c-3443.53,4172.35) -3438.87,4172.35 -3438.87,4158.37 cw(c-3443.53,4158.37) -3443.53,4153.71 -3516.66,4153.71 ccw(c-3516.66,4140.05) -3530.32,4140.05 -3530.32,4126.07 ccw(c-3516.66,4126.07) -3516.66,4112.41 -3443.53,4112.41 cw(c-3443.53,4107.75) -3438.87,4107.75 -3438.87,4093.77 cw(c-3443.53,4093.77) -3443.53,4089.11 -3516.66,4089.11 ccw(c-3516.66,4075.45) -3530.32,4075.45 -3530.32,4061.47 ccw(c-3516.66,4061.47) -3516.66,4047.81 -3443.53,4047.81 cw(c-3443.53,4043.15) -3438.87,4043.15 -3438.87,4029.17 cw(c-3443.53,4029.17) -3443.53,4024.51 -3516.66,4024.51 ccw(c-3516.66,4010.85) -3530.32,4010.85 -3530.32,3996.87 ccw(c-3516.66,3996.87) -3516.66,3983.21 -3443.53,3983.21 cw(c-3443.53,3978.55) -3438.87,3978.55 -3438.87,3964.57 cw(c-3443.53,3964.57) -3443.53,3959.91 -3516.66,3959.91 ccw(c-3516.66,3946.25) -3530.32,3946.25 -3530.32,3932.27 ccw(c-3516.66,3932.27) -3516.66,3918.61 -3443.53,3918.61 cw(c-3443.53,3913.95) -3438.87,3913.95 -3438.87,3899.97 cw(c-3443.53,3899.97) -3443.53,3895.31 -3508.35,3895.31 ccw(c-3508.35,3881.65) -3522.01,3881.65 -3522.01,3867.67 ccw(c-3508.35,3867.67) -3508.35,3854.01 -3484.98,3854.01 cw(c-3484.98,3849.35) -3480.32,3849.35 -3480.32,3843.2 -3480.32,3819.69 -3318.78,3658.15 -3318.78,3507.62 -3271.23,3460.07 -3259.87,3460.07 -3254.53,3454.72 MC1.177@-3231.89,3454.72
PORTA_S2_D0_N: J3.7 MC1.167 | length 3563.5
  L1-TOP w3.3: J3.7@-4204.65,5624.61 -4204.65,5587.86 -4198.3,5581.51 -4195.33,5581.51 -4193.4,5579.58 -4193.4,5572.38 -4178.51,5557.49 -4088.95,5557.49 -4079.46,5566.98 -4012.8,5566.98 -4010.27,5566.98 -3983.13,5539.84 -3983.13,5494.8 -3842.52,5354.19 -3842.52,5342.31 -3842.52,5318.25 cw(c-3848.18,5318.25) -3848.18,5312.59 -3849.17,5312.59 ccw(c-3849.17,5306.93) -3854.83,5306.93 -3854.83,5289.95 ccw(c-3849.17,5289.95) -3849.17,5284.29 -3848.18,5284.29 cw(c-3848.18,5278.63) -3842.52,5278.63 -3842.52,5276.98 -3842.52,5087.44 -3318.9,4563.82 -3318.9,4346.46 -3318.9,4283.55 ccw(c-3305.24,4283.55) -3305.24,4269.89 -3292.39,4269.89 cw(c-3292.39,4265.23) -3287.73,4265.23 -3287.73,4251.25 cw(c-3292.39,4251.25) -3292.39,4246.59 -3350.61,4246.59 ccw(c-3350.61,4232.93) -3364.27,4232.93 -3364.27,4218.95 ccw(c-3350.61,4218.95) -3350.61,4205.29 -3273.56,4205.29 cw(c-3273.56,4200.63) -3268.9,4200.63 -3268.9,4186.65 cw(c-3273.56,4186.65) -3273.56,4181.99 -3350.61,4181.99 ccw(c-3350.61,4168.33) -3364.27,4168.33 -3364.27,4154.35 ccw(c-3350.61,4154.35) -3350.61,4140.69 -3273.56,4140.69 cw(c-3273.56,4136.03) -3268.9,4136.03 -3268.9,4122.05 cw(c-3273.56,4122.05) -3273.56,4117.39 -3350.61,4117.39 ccw(c-3350.61,4103.73) -3364.27,4103.73 -3364.27,4089.75 ccw(c-3350.61,4089.75) -3350.61,4076.09 -3273.56,4076.09 cw(c-3273.56,4071.43) -3268.9,4071.43 -3268.9,4057.45 cw(c-3273.56,4057.45) -3273.56,4052.79 -3350.61,4052.79 ccw(c-3350.61,4039.13) -3364.27,4039.13 -3364.27,4025.15 ccw(c-3350.61,4025.15) -3350.61,4011.49 -3323.56,4011.49 cw(c-3323.56,4006.83) -3318.9,4006.83 -3318.9,4000.68 -3318.9,3773.24 -3152.42,3606.77 -3152.42,3571.46 -3152.42,3369.61 -3171.07,3350.96 -3203.91,3350.96 -3209.25,3356.3 MC1.167@-3231.89,3356.3
PORTA_S3_D1_N: J3.8 MC1.179 | length 3564.4
  L1-TOP w3.3: J3.8@-4204.65,5399.01 -4204.65,5435.76 -4198.3,5442.11 -4195.33,5442.11 -4193.4,5444.04 -4193.4,5451.24 -4165.46,5479.17 -4085.83,5479.17 -4060.79,5454.13 -4060.79,5315.1 -3972.73,5227.04 -3972.73,5115.4 -3471.32,4613.99 -3471.32,4322.83 -3471.32,4287.57 cw(c-3484.98,4287.57) -3484.98,4273.91 ccw(c-3484.98,4269.25) -3489.64,4269.25 -3489.64,4255.27 ccw(c-3484.98,4255.27) -3484.98,4250.61 -3447.28,4250.61 cw(c-3447.28,4236.95) -3433.62,4236.95 -3433.62,4222.97 cw(c-3447.28,4222.97) -3447.28,4209.31 -3516.66,4209.31 ccw(c-3516.66,4204.65) -3521.32,4204.65 -3521.32,4190.67 ccw(c-3516.66,4190.67) -3516.66,4186.01 -3443.53,4186.01 cw(c-3443.53,4172.35) -3429.87,4172.35 -3429.87,4158.37 cw(c-3443.53,4158.37) -3443.53,4144.71 -3516.66,4144.71 ccw(c-3516.66,4140.05) -3521.32,4140.05 -3521.32,4126.07 ccw(c-3516.66,4126.07) -3516.66,4121.41 -3443.53,4121.41 cw(c-3443.53,4107.75) -3429.87,4107.75 -3429.87,4093.77 cw(c-3443.53,4093.77) -3443.53,4080.11 -3516.66,4080.11 ccw(c-3516.66,4075.45) -3521.32,4075.45 -3521.32,4061.47 ccw(c-3516.66,4061.47) -3516.66,4056.81 -3443.53,4056.81 cw(c-3443.53,4043.15) -3429.87,4043.15 -3429.87,4029.17 cw(c-3443.53,4029.17) -3443.53,4015.51 -3516.66,4015.51 ccw(c-3516.66,4010.85) -3521.32,4010.85 -3521.32,3996.87 ccw(c-3516.66,3996.87) -3516.66,3992.21 -3443.53,3992.21 cw(c-3443.53,3978.55) -3429.87,3978.55 -3429.87,3964.57 cw(c-3443.53,3964.57) -3443.53,3950.91 -3516.66,3950.91 ccw(c-3516.66,3946.25) -3521.32,3946.25 -3521.32,3932.27 ccw(c-3516.66,3932.27) -3516.66,3927.61 -3443.53,3927.61 cw(c-3443.53,3913.95) -3429.87,3913.95 -3429.87,3899.97 cw(c-3443.53,3899.97) -3443.53,3886.31 -3508.35,3886.31 ccw(c-3508.35,3881.65) -3513.01,3881.65 -3513.01,3867.67 ccw(c-3508.35,3867.67) -3508.35,3863.01 -3484.98,3863.01 cw(c-3484.98,3849.35) -3471.32,3849.35 -3471.32,3843.2 -3471.32,3823.41 -3309.78,3661.88 -3309.78,3511.34 -3267.5,3469.07 -3259.87,3469.07 -3254.53,3474.41 MC1.179@-3231.89,3474.41
PORTA_S4_D2_P: J3.9 MC1.162 | length 3382.8
  L1-TOP w3.3: MC1.162@-2988.58,3297.24 -2965.94,3297.24 -2960.6,3302.59 -2848.45,3302.59 -2765.47,3385.57 -2765.47,3426.72 -2757.47,3434.72 v1(-2757.47,3437.01)
  L6-BOT w3.3: v2(-4240.46,5581.25) -4240.46,5579.01 -4247.5,5571.97 -4247.5,5549.06 -4226.18,5527.74 -4226.18,5499.88 -4201.55,5475.25 -3992.43,5475.25 -3580.24,5063.07 -3577.21,5060.03 -3557.79,5040.61 ccw(c-3553.79,5044.62) -3549.79,5040.62 -3538.54,5051.87 cw(c-3528.18,5041.5) -3517.81,5051.87 -3505.8,5039.86 cw(c-3516.17,5029.49) -3505.77,5019.16 -3530.27,4994.66 ; -3530.3,4994.63 ccw(c-3526.3,4990.63) -3530.3,4986.63 -3518.29,4974.62 ccw(c-3514.29,4978.62) -3510.29,4974.62 -3472.48,5012.43 -3472.29,5012.43 cw(c-3463.43,5000.74) -3453.07,5011.11 -3441.06,4999.1 cw(c-3451.43,4988.74) -3441.02,4978.41 -3464.3,4955.13 ccw(c-3460.3,4951.13) -3464.3,4947.12 -3436.61,4919.43 -3433.58,4916.4 -3168.17,4650.99 -3168.17,4198.23 -2907.2,3937.26 -2907.2,3700.88 -2765.47,3559.15 -2765.47,3447.29 -2757.47,3439.29 v1(-2757.47,3437.01)
PORTA_S5_D3_P: J3.10 MC1.169 | length 3381.9
  L1-TOP w3.3: v1(-4111.61,5228.35) -4111.61,5226.06 -4103.61,5218.06 -4103.61,5176.07 -3570.87,4643.32 -3570.87,4628.8 -3570.87,4622.65 ccw(c-3557.21,4622.65) -3557.21,4608.99 -3539.09,4608.99 cw(c-3539.09,4604.33) -3534.43,4604.33 -3534.43,4590.35 cw(c-3539.09,4590.35) -3539.09,4585.69 -3607.21,4585.69 ccw(c-3607.21,4572.03) -3620.87,4572.03 -3620.87,4558.05 ccw(c-3607.21,4558.05) -3607.21,4544.39 -3525.53,4544.39 cw(c-3525.53,4539.73) -3520.87,4539.73 -3520.87,4525.75 cw(c-3525.53,4525.75) -3525.53,4521.09 -3607.21,4521.09 ccw(c-3607.21,4507.43) -3620.87,4507.43 -3620.87,4493.45 ccw(c-3607.21,4493.45) -3607.21,4479.79 -3525.53,4479.79 cw(c-3525.53,4475.13) -3520.87,4475.13 -3520.87,4461.15 cw(c-3525.53,4461.15) -3525.53,4456.49 -3607.21,4456.49 ccw(c-3607.21,4442.83) -3620.87,4442.83 -3620.87,4428.85 ccw(c-3607.21,4428.85) -3607.21,4415.19 -3525.53,4415.19 cw(c-3525.53,4410.53) -3520.87,4410.53 -3520.87,4396.55 cw(c-3525.53,4396.55) -3525.53,4391.89 -3607.21,4391.89 ccw(c-3607.21,4378.23) -3620.87,4378.23 -3620.87,4364.25 ccw(c-3607.21,4364.25) -3607.21,4350.59 -3525.53,4350.59 cw(c-3525.53,4345.93) -3520.87,4345.93 -3520.87,4331.95 cw(c-3525.53,4331.95) -3525.53,4327.29 -3590.79,4327.29 ccw(c-3590.79,4313.63) -3604.45,4313.63 -3604.45,4299.65 ccw(c-3590.79,4299.65) -3590.79,4285.99 -3575.53,4285.99 cw(c-3575.53,4281.33) -3570.87,4281.33 -3570.87,4232.28 -3570.87,3852.75 -3359.43,3641.31 -3359.43,3469.53 -3271.23,3381.33 -3259.87,3381.33 -3254.53,3375.98 MC1.169@-3231.89,3375.98
  L6-BOT w3.3: v2(-4240.46,5355.65) -4240.46,5353.41 -4247.5,5346.37 -4247.5,5301.03 -4237.52,5291.05 -4225.19,5278.71 ccw(c-4221.18,5282.72) -4217.18,5278.71 -4216.49,5279.41 cw(c-4212.48,5275.41) -4208.48,5279.41 -4196.47,5267.4 cw(c-4200.48,5263.4) -4196.47,5259.4 -4197.17,5258.7 ccw(c-4193.17,5254.7) -4197.17,5250.7 -4175.99,5229.52 -4138.26,5191.79 -4120.19,5191.79 -4103.61,5208.37 -4103.61,5218.06 -4111.61,5226.06 v1(-4111.61,5228.35)
PORTA_S6_D2_N: J3.11 MC1.164 | length 3382.8
  L1-TOP w3.3: MC1.164@-2988.58,3316.93 -2965.94,3316.93 -2960.6,3311.59 -2852.18,3311.59 -2837.46,3326.31 -2836.29,3327.47 ccw(c-2840.29,3331.48) -2836.29,3335.48 -2837,3336.19 cw(c-2833,3340.19) -2837,3344.19 -2824.99,3356.2 cw(c-2820.99,3352.2) -2816.99,3356.2 -2816.28,3355.49 ccw(c-2812.28,3359.49) -2808.27,3355.49 -2790.54,3373.22 -2774.47,3389.3 -2774.47,3426.72 -2782.47,3434.72 v1(-2782.47,3437.01)
  L6-BOT w3.3: v2(-4263.53,5581.25) -4263.53,5579.01 -4256.5,5571.97 -4256.5,5545.33 -4235.18,5524.01 -4235.18,5496.15 -4205.28,5466.25 -3996.16,5466.25 -3586.61,5056.7 -3583.58,5053.67 -3564.19,5034.28 ccw(c-3553.79,5044.62) -3543.43,5034.25 -3532.18,5045.5 cw(c-3528.18,5041.5) -3524.17,5045.5 -3512.17,5033.5 cw(c-3516.17,5029.49) -3512.17,5025.49 -3537.98,4999.68 -3537.98,4999.48 ccw(c-3526.3,4990.63) -3536.64,4980.24 -3524.68,4968.29 ccw(c-3514.29,4978.62) -3503.92,4968.26 -3467.46,5004.72 ; -3467.44,5004.74 cw(c-3463.43,5000.74) -3459.43,5004.74 -3447.42,4992.74 cw(c-3451.43,4988.74) -3447.42,4984.73 -3470.67,4961.49 ccw(c-3460.3,4951.13) -3470.67,4940.76 -3442.97,4913.07 -3439.94,4910.04 -3177.17,4647.26 -3177.17,4194.5 -2916.2,3933.54 -2916.2,3697.15 -2774.47,3555.42 -2774.47,3447.29 -2782.47,3439.29 v1(-2782.47,3437.01)
PORTA_S7_D3_N: J3.12 MC1.171 | length 3382
  L1-TOP w3.3: v1(-4086.61,5228.35) -4086.61,5226.06 -4094.61,5218.06 -4094.61,5179.8 -3561.87,4647.05 -3561.87,4628.8 -3561.87,4622.65 ccw(c-3557.21,4622.65) -3557.21,4617.99 -3539.09,4617.99 cw(c-3539.09,4604.33) -3525.43,4604.33 -3525.43,4590.35 cw(c-3539.09,4590.35) -3539.09,4576.69 -3607.21,4576.69 ccw(c-3607.21,4572.03) -3611.87,4572.03 -3611.87,4558.05 ccw(c-3607.21,4558.05) -3607.21,4553.39 -3525.53,4553.39 cw(c-3525.53,4539.73) -3511.87,4539.73 -3511.87,4525.75 cw(c-3525.53,4525.75) -3525.53,4512.09 -3607.21,4512.09 ccw(c-3607.21,4507.43) -3611.87,4507.43 -3611.87,4493.45 ccw(c-3607.21,4493.45) -3607.21,4488.79 -3525.53,4488.79 cw(c-3525.53,4475.13) -3511.87,4475.13 -3511.87,4461.15 cw(c-3525.53,4461.15) -3525.53,4447.49 -3607.21,4447.49 ccw(c-3607.21,4442.83) -3611.87,4442.83 -3611.87,4428.85 ccw(c-3607.21,4428.85) -3607.21,4424.19 -3525.53,4424.19 cw(c-3525.53,4410.53) -3511.87,4410.53 -3511.87,4396.55 cw(c-3525.53,4396.55) -3525.53,4382.89 -3607.21,4382.89 ccw(c-3607.21,4378.23) -3611.87,4378.23 -3611.87,4364.25 ccw(c-3607.21,4364.25) -3607.21,4359.59 -3525.53,4359.59 cw(c-3525.53,4345.93) -3511.87,4345.93 -3511.87,4331.95 cw(c-3525.53,4331.95) -3525.53,4318.29 -3590.79,4318.29 ccw(c-3590.79,4313.63) -3595.45,4313.63 -3595.45,4299.65 ccw(c-3590.79,4299.65) -3590.79,4294.99 -3575.53,4294.99 cw(c-3575.53,4281.33) -3561.87,4281.33 -3561.87,4232.28 -3561.87,3856.48 -3350.43,3645.04 -3350.43,3473.25 -3267.5,3390.33 -3259.87,3390.33 -3254.53,3395.67 MC1.171@-3231.89,3395.67
  L6-BOT w3.3: v2(-4263.53,5355.65) -4263.53,5353.41 -4256.5,5346.37 -4256.5,5297.3 -4141.99,5182.79 -4116.47,5182.79 -4094.61,5204.64 -4094.61,5218.06 -4086.61,5226.06 v1(-4086.61,5228.35)
PORTA_S8_D4_P: J3.13 MC1.170 | length 3385.5
  L1-TOP w3.3: MC1.170@-2988.58,3375.98 -2965.94,3375.98 -2960.6,3381.33 -2883.88,3381.33 -2840.27,3424.94 -2840.27,3493.65 -2832.27,3501.65 v1(-2832.27,3503.94)
  L6-BOT w3.3: v2(-4303.36,5667.97) -4303.36,5665.72 -4310.4,5658.69 -4310.4,5552.9 -4281.29,5523.8 -4281.29,5468.68 -4146.14,5333.52 -3980.62,5333.52 -3821.39,5174.29 -3818.36,5171.26 -3788.25,5141.15 cw(c-3798.61,5130.78) -3788.25,5120.42 ccw(c-3784.24,5116.41) -3788.25,5112.42 -3776.24,5100.4 ccw(c-3772.24,5104.41) -3768.24,5100.4 -3760.07,5108.57 -3759.88,5108.57 cw(c-3751.02,5096.89) -3740.66,5107.25 -3728.65,5095.25 ; -3728.65,5095.25 cw(c-3739.01,5084.88) -3728.65,5074.51 -3735.5,5067.66 ccw(c-3731.49,5063.66) -3735.5,5059.67 -3723.48,5047.65 ccw(c-3719.49,5051.66) -3715.49,5047.65 cw(c-3705.12,5037.29) -3696.27,5048.97 -3696.07,5048.97 -3694.77,5047.67 -3693.43,5046.34 -3690.4,5043.31 -3334.49,4687.39 -3334.49,3779.37 -3220.07,3664.95 -3046.22,3664.95 -3016.01,3695.16 -2964.31,3695.16 -2840.27,3571.12 -2840.27,3514.22 -2832.27,3506.22 v1(-2832.27,3503.94)
PORTA_S9_D5_P: J3.14 MC1.149 | length 3567
  L1-TOP w3.3: -4485.86,5076.82 ccw(c-4489.88,5072.83) -4493.88,5076.83 -4496.94,5073.77 cw(c-4507.31,5084.14) -4517.7,5073.79 -4529.65,5085.75 cw(c-4519.32,5096.14) -4529.68,5106.51 -4526.62,5109.57 ccw(c-4530.62,5113.57) -4526.64,5117.59 -4564.45,5155.4 -4567.48,5158.43 -4757.03,5347.99 -4757.03,5447.21 -4727.12,5477.11 -4328.94,5477.11 -4310.4,5458.58 -4310.4,5444.04 -4308.47,5442.11 -4305.5,5442.11 -4299.15,5435.76 J3.14@-4299.15,5399.01 ; -4485.85,5076.8 -4484.56,5075.52 -4481.53,5072.48 -4376.42,4967.38 -4295.07,4967.38 -3921.26,4593.57 -3921.26,3822.16 -3531.5,3432.4 -3531.5,3415.51 -3443.2,3327.21 -3443.2,3296.61 -3331.06,3184.48 -3259.87,3184.48 -3254.53,3179.13 MC1.149@-3231.89,3179.13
